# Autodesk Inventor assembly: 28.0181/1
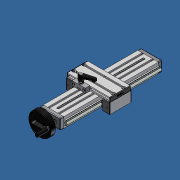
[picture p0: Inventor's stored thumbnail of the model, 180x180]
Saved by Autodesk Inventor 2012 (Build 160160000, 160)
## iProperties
Created: 2007-06
Part Number: 28.0181/1
Document SubType Name: Assembly
Designer: Andy Moles
Description: ADJUSTING UNIT VEW 45X90F WITH TOP LOCK
Author: Andy Moles
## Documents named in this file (20)
- C:\Andys Backup Data\ANDY'S INVENTOR\INVENTOR LIBRARIES\PARTS LIBRARY\READY FOR USE MODULES LG\28.0181_1 ADJUSTING UNIT VEW 45X90F WITH TOP CLAMP.iam
- C:\Andys Backup Data\ANDY'S INVENTOR\INVENTOR LIBRARIES\PARTS LIBRARY\FASTENING ELEMENTS\NUTS\21.1351 M8 SQUARE NUT.ipt
- C:\Andys Backup Data\ANDY'S INVENTOR\INVENTOR LIBRARIES\PARTS LIBRARY\READY FOR USE MODULES LG\SUBCOMPONENTS\50.1264 BALL BEARING 10X30X9 6200 2RS DIN 625.ipt
- C:\Andys Backup Data\ANDY'S INVENTOR\INVENTOR LIBRARIES\PARTS LIBRARY\READY FOR USE MODULES LG\SUBCOMPONENTS\28.0201 BEARING PLATE 45X90 IDLER SIDE.ipt
- C:\Andys Backup Data\ANDY'S INVENTOR\INVENTOR LIBRARIES\PARTS LIBRARY\READY FOR USE MODULES LG\SUBCOMPONENTS\28.0200 BEARING PLATE 45X90 HANDWHEEL SIDE.ipt
- C:\Andys Backup Data\ANDY'S INVENTOR\INVENTOR LIBRARIES\PARTS LIBRARY\READY FOR USE MODULES LG\SUBCOMPONENTS\28.0204 HANDWHEEL 100mm.iam
- C:\Andys Backup Data\ANDY'S INVENTOR\INVENTOR LIBRARIES\PARTS LIBRARY\FASTENING ELEMENTS\SCREWS CAP\21.1204 M8X25.ipt
- C:\Andys Backup Data\ANDY'S INVENTOR\INVENTOR LIBRARIES\PARTS LIBRARY\READY FOR USE MODULES LG\SUBCOMPONENTS\28.0221_1 ACME SCREW 16X4 TOP LOCK.ipt
- C:\Andys Backup Data\ANDY'S INVENTOR\INVENTOR LIBRARIES\PARTS LIBRARY\FASTENING ELEMENTS\WASHERS\21.1326 DISC SPRING 20.ipt
- C:\Andys Backup Data\ANDY'S INVENTOR\INVENTOR LIBRARIES\PARTS LIBRARY\READY FOR USE MODULES LG\SUBCOMPONENTS\28.0215_2 RAIL 45X90F FOR TOP LOCK.iam
- C:\Andys Backup Data\ANDY'S INVENTOR\INVENTOR LIBRARIES\PARTS LIBRARY\READY FOR USE MODULES LG\SUBCOMPONENTS\28.0257 BRONZE NUT 16X4 NOTCHED.ipt
- C:\Andys Backup Data\ANDY'S INVENTOR\INVENTOR LIBRARIES\PARTS LIBRARY\READY FOR USE MODULES LG\SUBCOMPONENTS\28.0225_1 LWG 32X45-90 90X19-NSC.ipt
- C:\Andys Backup Data\ANDY'S INVENTOR\INVENTOR LIBRARIES\PARTS LIBRARY\READY FOR USE MODULES LG\SUBCOMPONENTS\28.0126 SLIDE 45X32.ipt
- C:\Andys Backup Data\ANDY'S INVENTOR\INVENTOR LIBRARIES\PARTS LIBRARY\COMPONENTS LG\22.1094 SLIDE RAIL LG.iam
- C:\Andys Backup Data\ANDY'S INVENTOR\INVENTOR LIBRARIES\PARTS LIBRARY\END CAPS\22.1014_1 END CAP 90X19 GRAY.ipt
- C:\Andys Backup Data\ANDY'S INVENTOR\INVENTOR LIBRARIES\PARTS LIBRARY\READY FOR USE MODULES LG\SUBCOMPONENTS\28.0254 NUT SLIDE CONNECTOR 16.ipt
- C:\Andys Backup Data\ANDY'S INVENTOR\INVENTOR LIBRARIES\PARTS LIBRARY\FASTENING ELEMENTS\SCREWS CAP\21.1235 M5X16.ipt
- C:\Andys Backup Data\ANDY'S INVENTOR\INVENTOR LIBRARIES\PARTS LIBRARY\FASTENING ELEMENTS\SCREWS CAP\21.1200 M8X16.ipt
- C:\Andys Backup Data\ANDY'S INVENTOR\INVENTOR LIBRARIES\PARTS LIBRARY\END CAPS\22.1003_1 END CAP 45x32 Z Gray.iam
- C:\Andys Backup Data\ANDY'S INVENTOR\INVENTOR LIBRARIES\PARTS LIBRARY\COMPONENTS LR\28.0270_9 SLIDE CLAMPING UNIT 2mm OFFSET..iam
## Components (37 placed, 19 different names)
1. 28.0215_2 RAIL 45X90F FOR TOP LOCK:1 [sub-assembly] — Mate:13, Flush:4, Flush:5, Flush:6, Mate:14, Flush:7, Mate:16, Flush:8, Flush:9, Angle:1, Angle:2, Mate:24
2. 50.1264 10X30X9 6200 2RS DIN 625 BALL BEARING:1 — Insert:11, Insert:14
3. 50.1264 10X30X9 6200 2RS DIN 625 BALL BEARING:2 — Insert:10
4. 28.0201 BEARING PLATE 45X90 IDLER SIDE:1 — Insert:6, Insert:7, Insert:10, Flush:5, Mate:16, Flush:8
5. 28.0200 BEARING PLATE 45X90 HANDWHEEL SIDE:1 — Insert:5, Insert:8, Insert:9, Insert:11, Mate:13, Flush:4, Flush:9
6. 28.0204 HANDWHEEL 100mm:1 [sub-assembly] — Insert:5
7. 21.1204  M8 x 25:1 — Insert:7
8. 21.1204  M8 x 25:2 — Insert:6
9. 21.1204  M8 x 25:3 — Insert:8
10. 21.1204  M8 x 25:4 — Insert:9
11. 28.0221_1 ACME SCREW 16X4 TOP LOCK:1 — Insert:12, Insert:13, Mate:17
12. 21.1326 DISC SPRING 20:1 — Insert:12, Insert:14
13. 21.1326 DISC SPRING 20:2 — Insert:13
14. 28.0257 BRONZE NUT 16X4 NOTCHED:1 — Angle:1, Mate:17, Mate:29
15. 28.0225_1 LWG 32X45-90 90X19-NSC:1 — Mate:18, Flush:10, Flush:11, Mate:19, Flush:12, Flush:13, Angle:2, Mate:25, Flush:16, Flush:17, Mate:26, Flush:18, Flush:19, Mate:27, Insert:15, Mate:28, Insert:16, Insert:17, Insert:18, Insert:19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
16. 28.0126 SLIDE 45X32:1 — Mate:18, Flush:10, Flush:11, Mate:22, Flush:15, Mate:23, Insert:27, Insert:28
17. 28.0126 SLIDE 45X32:2 — Mate:19, Flush:12, Flush:13, Mate:20, Flush:14, Mate:21, Insert:26, Insert:29
18. 22.1094 SLIDE RAIL LG:1 [sub-assembly] — Mate:20, Flush:14, Mate:21
19. 22.1094 SLIDE RAIL LG:2 [sub-assembly] — Mate:22, Flush:15, Mate:23, Mate:24
20. 22.1014_1 END CAP 90X19 GRAY:1 — Mate:25, Flush:16, Flush:17, Angle:3
21. 22.1014_1 END CAP 90X19 GRAY:2 — Mate:26, Flush:18, Flush:19
22. 28.0254 NUT SLIDE CONNECTOR 16:1 — Mate:27, Insert:15, Mate:28, Mate:29
23. 21.1235  M5 x 16:1 — Insert:17
24. 21.1235  M5 x 16:2 — Insert:16
25. 21.1200 M8 x 16:1 — Insert:18
26. 21.1200 M8 x 16:2 — Insert:19
27. 21.1200 M8 x 16:3 — Insert:20
28. 21.1200 M8 x 16:4 — Insert:21
29. 21.1351 M8 SQUARE NUT:1 — Insert:22, Angle:3
30. 21.1351 M8 SQUARE NUT:2 — Insert:23
31. 21.1351 M8 SQUARE NUT:3 — Insert:24, Angle:4
32. 21.1351 M8 SQUARE NUT:4 — Insert:25, Angle:5
33. 22.1003\1 END CAP 45x32 Z Gray:1 [sub-assembly] — Insert:26, Angle:9
34. 22.1003\1 END CAP 45x32 Z Gray:2 [sub-assembly] — Insert:29, Angle:6
35. 22.1003\1 END CAP 45x32 Z Gray:3 [sub-assembly] — Insert:28, Angle:7
36. 22.1003\1 END CAP 45x32 Z Gray:4 [sub-assembly] — Insert:27, Angle:8
37. 28.0270_9 SLIDE CLAMPING UNIT 2mm OFFSET.:1 [sub-assembly] — Mate:30, Mate:31, Flush:20
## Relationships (69: Insert 25, Mate 18, Flush 17, Angle 9)
- Insert:5: 28.0200 BEARING PLATE 45X90 HANDWHEEL SIDE:1 ↔ 28.0204 HANDWHEEL 100mm:1
- Insert:6: 28.0201 BEARING PLATE 45X90 IDLER SIDE:1 ↔ 21.1204  M8 x 25:2
- Insert:7: 28.0201 BEARING PLATE 45X90 IDLER SIDE:1 ↔ 21.1204  M8 x 25:1
- Insert:8: 28.0200 BEARING PLATE 45X90 HANDWHEEL SIDE:1 ↔ 21.1204  M8 x 25:3
- Insert:9: 28.0200 BEARING PLATE 45X90 HANDWHEEL SIDE:1 ↔ 21.1204  M8 x 25:4
- Insert:10: 50.1264 10X30X9 6200 2RS DIN 625 BALL BEARING:2 ↔ 28.0201 BEARING PLATE 45X90 IDLER SIDE:1
- Insert:11: 50.1264 10X30X9 6200 2RS DIN 625 BALL BEARING:1 ↔ 28.0200 BEARING PLATE 45X90 HANDWHEEL SIDE:1
- Mate:13: 28.0215_2 RAIL 45X90F FOR TOP LOCK:1 ↔ 28.0200 BEARING PLATE 45X90 HANDWHEEL SIDE:1
- Flush:4: 28.0215_2 RAIL 45X90F FOR TOP LOCK:1 ↔ 28.0200 BEARING PLATE 45X90 HANDWHEEL SIDE:1
- Flush:5: 28.0215_2 RAIL 45X90F FOR TOP LOCK:1 ↔ 28.0201 BEARING PLATE 45X90 IDLER SIDE:1
- Flush:6: 28.0215_2 RAIL 45X90F FOR TOP LOCK:1
- Mate:14: 28.0215_2 RAIL 45X90F FOR TOP LOCK:1
- Flush:7: 28.0215_2 RAIL 45X90F FOR TOP LOCK:1
- Mate:16: 28.0215_2 RAIL 45X90F FOR TOP LOCK:1 ↔ 28.0201 BEARING PLATE 45X90 IDLER SIDE:1
- Flush:8: 28.0215_2 RAIL 45X90F FOR TOP LOCK:1 ↔ 28.0201 BEARING PLATE 45X90 IDLER SIDE:1
- Flush:9: 28.0215_2 RAIL 45X90F FOR TOP LOCK:1 ↔ 28.0200 BEARING PLATE 45X90 HANDWHEEL SIDE:1
- Insert:12: 28.0221_1 ACME SCREW 16X4 TOP LOCK:1 ↔ 21.1326 DISC SPRING 20:1
- Insert:13: 28.0221_1 ACME SCREW 16X4 TOP LOCK:1 ↔ 21.1326 DISC SPRING 20:2
- Insert:14: 50.1264 10X30X9 6200 2RS DIN 625 BALL BEARING:1 ↔ 21.1326 DISC SPRING 20:1
- Angle:1: 28.0215_2 RAIL 45X90F FOR TOP LOCK:1 ↔ 28.0257 BRONZE NUT 16X4 NOTCHED:1
- Mate:17: 28.0221_1 ACME SCREW 16X4 TOP LOCK:1 ↔ 28.0257 BRONZE NUT 16X4 NOTCHED:1
- Mate:18: 28.0225_1 LWG 32X45-90 90X19-NSC:1 ↔ 28.0126 SLIDE 45X32:1
- Flush:10: 28.0225_1 LWG 32X45-90 90X19-NSC:1 ↔ 28.0126 SLIDE 45X32:1
- Flush:11: 28.0225_1 LWG 32X45-90 90X19-NSC:1 ↔ 28.0126 SLIDE 45X32:1
- Mate:19: 28.0225_1 LWG 32X45-90 90X19-NSC:1 ↔ 28.0126 SLIDE 45X32:2
- Flush:12: 28.0225_1 LWG 32X45-90 90X19-NSC:1 ↔ 28.0126 SLIDE 45X32:2
- Flush:13: 28.0225_1 LWG 32X45-90 90X19-NSC:1 ↔ 28.0126 SLIDE 45X32:2
- Mate:20: 28.0126 SLIDE 45X32:2 ↔ 22.1094 SLIDE RAIL LG:1
- Flush:14: 28.0126 SLIDE 45X32:2 ↔ 22.1094 SLIDE RAIL LG:1
- Mate:21: 28.0126 SLIDE 45X32:2 ↔ 22.1094 SLIDE RAIL LG:1
- Mate:22: 28.0126 SLIDE 45X32:1 ↔ 22.1094 SLIDE RAIL LG:2
- Flush:15: 28.0126 SLIDE 45X32:1 ↔ 22.1094 SLIDE RAIL LG:2
- Mate:23: 28.0126 SLIDE 45X32:1 ↔ 22.1094 SLIDE RAIL LG:2
- Angle:2: 28.0215_2 RAIL 45X90F FOR TOP LOCK:1 ↔ 28.0225_1 LWG 32X45-90 90X19-NSC:1
- Mate:24: 28.0215_2 RAIL 45X90F FOR TOP LOCK:1 ↔ 22.1094 SLIDE RAIL LG:2
- Mate:25: 28.0225_1 LWG 32X45-90 90X19-NSC:1 ↔ 22.1014_1 END CAP 90X19 GRAY:1
- Flush:16: 28.0225_1 LWG 32X45-90 90X19-NSC:1 ↔ 22.1014_1 END CAP 90X19 GRAY:1
- Flush:17: 28.0225_1 LWG 32X45-90 90X19-NSC:1 ↔ 22.1014_1 END CAP 90X19 GRAY:1
- Mate:26: 28.0225_1 LWG 32X45-90 90X19-NSC:1 ↔ 22.1014_1 END CAP 90X19 GRAY:2
- Flush:18: 28.0225_1 LWG 32X45-90 90X19-NSC:1 ↔ 22.1014_1 END CAP 90X19 GRAY:2
- Flush:19: 28.0225_1 LWG 32X45-90 90X19-NSC:1 ↔ 22.1014_1 END CAP 90X19 GRAY:2
- Mate:27: 28.0225_1 LWG 32X45-90 90X19-NSC:1 ↔ 28.0254 NUT SLIDE CONNECTOR 16:1
- Insert:15: 28.0225_1 LWG 32X45-90 90X19-NSC:1 ↔ 28.0254 NUT SLIDE CONNECTOR 16:1
- Mate:28: 28.0225_1 LWG 32X45-90 90X19-NSC:1 ↔ 28.0254 NUT SLIDE CONNECTOR 16:1
- Mate:29: 28.0257 BRONZE NUT 16X4 NOTCHED:1 ↔ 28.0254 NUT SLIDE CONNECTOR 16:1
- Insert:16: 28.0225_1 LWG 32X45-90 90X19-NSC:1 ↔ 21.1235  M5 x 16:2
- Insert:17: 28.0225_1 LWG 32X45-90 90X19-NSC:1 ↔ 21.1235  M5 x 16:1
- Insert:18: 28.0225_1 LWG 32X45-90 90X19-NSC:1 ↔ 21.1200 M8 x 16:1
- Insert:19: 28.0225_1 LWG 32X45-90 90X19-NSC:1 ↔ 21.1200 M8 x 16:2
- Insert:20: 28.0225_1 LWG 32X45-90 90X19-NSC:1 ↔ 21.1200 M8 x 16:3
- Insert:21: 28.0225_1 LWG 32X45-90 90X19-NSC:1 ↔ 21.1200 M8 x 16:4
- Insert:22: 28.0225_1 LWG 32X45-90 90X19-NSC:1 ↔ 21.1351 M8 SQUARE NUT:1
- Angle:3: 22.1014_1 END CAP 90X19 GRAY:1 ↔ 21.1351 M8 SQUARE NUT:1
- Insert:23: 28.0225_1 LWG 32X45-90 90X19-NSC:1 ↔ 21.1351 M8 SQUARE NUT:2
- Insert:24: 28.0225_1 LWG 32X45-90 90X19-NSC:1 ↔ 21.1351 M8 SQUARE NUT:3
- Angle:4: 28.0225_1 LWG 32X45-90 90X19-NSC:1 ↔ 21.1351 M8 SQUARE NUT:3
- Insert:25: 28.0225_1 LWG 32X45-90 90X19-NSC:1 ↔ 21.1351 M8 SQUARE NUT:4
- Angle:5: 28.0225_1 LWG 32X45-90 90X19-NSC:1 ↔ 21.1351 M8 SQUARE NUT:4
- Insert:26: 28.0126 SLIDE 45X32:2 ↔ 22.1003\1 END CAP 45x32 Z Gray:1
- Insert:27: 28.0126 SLIDE 45X32:1 ↔ 22.1003\1 END CAP 45x32 Z Gray:4
- Insert:28: 28.0126 SLIDE 45X32:1 ↔ 22.1003\1 END CAP 45x32 Z Gray:3
- Insert:29: 28.0126 SLIDE 45X32:2 ↔ 22.1003\1 END CAP 45x32 Z Gray:2
- Angle:6: 28.0225_1 LWG 32X45-90 90X19-NSC:1 ↔ 22.1003\1 END CAP 45x32 Z Gray:2
- Angle:7: 28.0225_1 LWG 32X45-90 90X19-NSC:1 ↔ 22.1003\1 END CAP 45x32 Z Gray:3
- Angle:8: 28.0225_1 LWG 32X45-90 90X19-NSC:1 ↔ 22.1003\1 END CAP 45x32 Z Gray:4
- Angle:9: 28.0225_1 LWG 32X45-90 90X19-NSC:1 ↔ 22.1003\1 END CAP 45x32 Z Gray:1
- Mate:30: 28.0225_1 LWG 32X45-90 90X19-NSC:1 ↔ 28.0270_9 SLIDE CLAMPING UNIT 2mm OFFSET.:1
- Mate:31: 28.0225_1 LWG 32X45-90 90X19-NSC:1 ↔ 28.0270_9 SLIDE CLAMPING UNIT 2mm OFFSET.:1
- Flush:20: 28.0225_1 LWG 32X45-90 90X19-NSC:1 ↔ 28.0270_9 SLIDE CLAMPING UNIT 2mm OFFSET.:1
